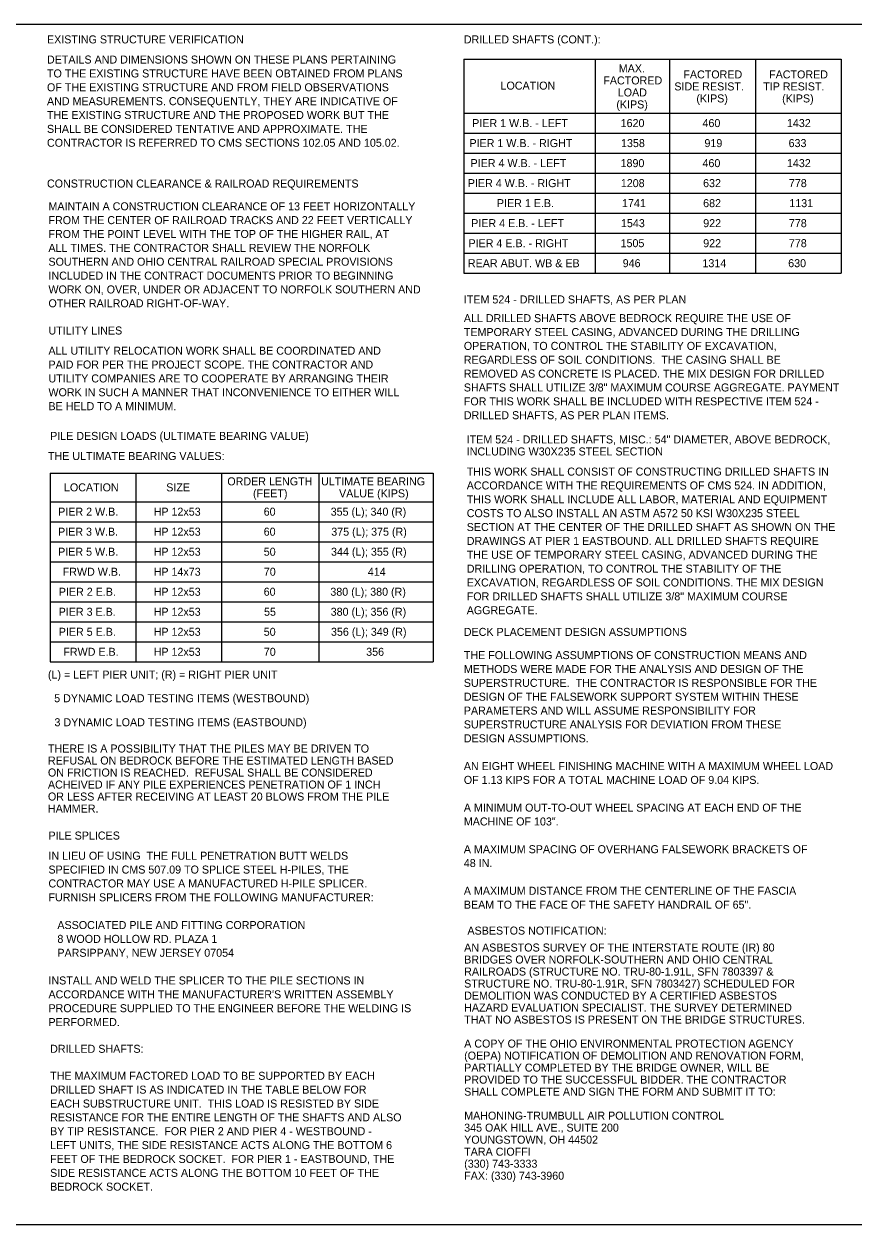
# Model space of a CAD drawing. Extents: x 1530552 to 1530730, y 675304 to 675366.
# Drawn here: x 1530707.49 to 1530722.01, y 675331.91 to 675352.91 of the extents above; entities that cross this region are included whole.
import ezdxf

# ---------------------------------------------------------------- set-up
doc = ezdxf.new("R2010")
doc.units = 0
doc.layers.add('BR_P_Gen_Text', color=7, linetype='Continuous')
doc.layers.add('Default', color=7, linetype='Continuous')

msp = doc.modelspace()

# ---------------------------------------------------------------- linework, layer by layer
at = {"layer": 'BR_P_Gen_Text'}
for p, q in [((1530715.188, 675352.298), (1530715.188, 675348.557)), ((1530715.188, 675352.298), (1530721.788, 675352.298)), ((1530717.488, 675352.298), (1530717.488, 675348.557)), ((1530718.788, 675352.298), (1530718.788, 675348.557)), ((1530720.288, 675352.298), (1530720.288, 675348.557)), ((1530721.788, 675352.298), (1530721.788, 675348.557)), ((1530715.188, 675351.357), (1530721.788, 675351.357)), ((1530715.188, 675351.007), (1530721.788, 675351.007)), ((1530715.188, 675350.657), (1530721.788, 675350.657)), ((1530715.188, 675350.307), (1530721.788, 675350.307)), ((1530715.188, 675349.957), (1530721.788, 675349.957)), ((1530715.188, 675349.607), (1530721.788, 675349.607)), ((1530715.188, 675349.257), (1530721.788, 675349.257)), ((1530715.188, 675348.907), (1530721.788, 675348.907)), ((1530715.188, 675348.557), (1530721.788, 675348.557)), ((1530707.951, 675345.062), (1530707.951, 675341.762)), ((1530707.951, 675345.062), (1530714.651, 675345.062)), ((1530709.451, 675345.062), (1530709.451, 675341.762)), ((1530710.951, 675345.062), (1530710.951, 675341.762)), ((1530712.651, 675345.062), (1530712.651, 675341.762)), ((1530714.651, 675345.062), (1530714.651, 675341.762)), ((1530707.951, 675344.562), (1530714.651, 675344.562)), ((1530707.951, 675344.212), (1530714.651, 675344.212)), ((1530707.951, 675343.862), (1530714.651, 675343.862)), ((1530707.951, 675343.512), (1530714.651, 675343.512)), ((1530707.951, 675343.162), (1530714.651, 675343.162)), ((1530707.951, 675342.812), (1530714.651, 675342.812)), ((1530707.951, 675342.462), (1530714.651, 675342.462)), ((1530707.951, 675342.112), (1530714.651, 675342.112)), ((1530707.951, 675341.762), (1530714.651, 675341.762))]:
    msp.add_line(p, q, dxfattribs=at)
msp.add_lwpolyline([(1530699.468, 675352.914), (1530729.968, 675352.914), (1530729.968, 675331.914), (1530699.468, 675331.914)], close=True, dxfattribs=at)

# ---------------------------------------------------------------- texts
for s, p in [('EXISTING STRUCTURE VERIFICATION', (1530707.896, 675352.575)), ('DRILLED SHAFTS (CONT.):', (1530715.188, 675352.575)), ('DETAILS AND DIMENSIONS SHOWN ON THESE PLANS PERTAINING ', (1530707.896, 675352.223)), ('TO THE EXISTING STRUCTURE HAVE BEEN OBTAINED FROM PLANS ', (1530707.896, 675351.98)), ('MAX. ', (1530717.898, 675352.068)), ('FACTORED', (1530719.028, 675351.963)), ('FACTORED', (1530720.528, 675351.963)), ('OF THE EXISTING STRUCTURE AND FROM FIELD OBSERVATIONS ', (1530707.896, 675351.738)), ('LOCATION', (1530715.83, 675351.767)), ('FACTORED', (1530717.628, 675351.858)), ('SIDE RESIST.', (1530718.87, 675351.753)), ('TIP RESIST.', (1530720.425, 675351.753)), ('AND MEASUREMENTS. CONSEQUENTLY, THEY ARE INDICATIVE OF ', (1530707.896, 675351.495)), ('LOAD', (1530717.881, 675351.648)), ('(KIPS)', (1530719.256, 675351.543)), ('(KIPS)', (1530720.756, 675351.543)), ('THE EXISTING STRUCTURE AND THE PROPOSED WORK BUT THE ', (1530707.896, 675351.253)), ('(KIPS)', (1530717.856, 675351.438)), ('PIER 1 W.B. - LEFT', (1530715.334, 675351.112)), ('1620', (1530717.931, 675351.112)), ('460', (1530719.363, 675351.112)), ('1432', (1530720.84, 675351.112)), ('SHALL BE CONSIDERED TENTATIVE AND APPROXIMATE. THE ', (1530707.896, 675351.011)), ('CONTRACTOR IS REFERRED TO CMS SECTIONS 102.05 AND 105.02.', (1530707.896, 675350.768)), ('PIER 1 W.B. - RIGHT', (1530715.286, 675350.762)), ('1358', (1530717.938, 675350.762)), ('919', (1530719.397, 675350.762)), ('633', (1530720.869, 675350.762)), ('PIER 4 W.B. - LEFT', (1530715.306, 675350.412)), ('1890', (1530717.93, 675350.412)), ('460', (1530719.363, 675350.412)), ('1432', (1530720.84, 675350.412)), ('CONSTRUCTION CLEARANCE & RAILROAD REQUIREMENTS', (1530707.896, 675350.055)), ('PIER 4 W.B. - RIGHT', (1530715.258, 675350.062)), ('1208', (1530717.934, 675350.062)), ('632', (1530719.373, 675350.062)), ('778', (1530720.874, 675350.062)), ('MAINTAIN A CONSTRUCTION CLEARANCE OF 13 FEET HORIZONTALLY ', (1530707.922, 675349.657)), ('PIER 1 E.B.', (1530715.767, 675349.712)), ('1741', (1530717.955, 675349.712)), ('682', (1530719.374, 675349.712)), ('1131', (1530720.881, 675349.712)), ('FROM THE CENTER OF RAILROAD TRACKS AND 22 FEET VERTICALLY ', (1530707.922, 675349.415)), ('PIER 4 E.B. - LEFT', (1530715.317, 675349.362)), ('1543', (1530717.937, 675349.362)), ('922', (1530719.375, 675349.362)), ('778', (1530720.874, 675349.362)), ('FROM THE POINT LEVEL WITH THE TOP OF THE HIGHER RAIL, AT ', (1530707.922, 675349.173)), ('PIER 4 E.B. - RIGHT', (1530715.269, 675349.012)), ('1505', (1530717.93, 675349.012)), ('922', (1530719.375, 675349.012)), ('778', (1530720.874, 675349.012)), ('ALL TIMES. THE CONTRACTOR SHALL REVIEW THE NORFOLK ', (1530707.922, 675348.93)), ('SOUTHERN AND OHIO CENTRAL RAILROAD SPECIAL PROVISIONS ', (1530707.922, 675348.688)), ('REAR ABUT. WB & EB', (1530715.259, 675348.662)), ('946', (1530717.967, 675348.662)), ('1314', (1530719.362, 675348.662)), ('630', (1530720.862, 675348.662)), ('INCLUDED IN THE CONTRACT DOCUMENTS PRIOR TO BEGINNING ', (1530707.922, 675348.445)), ('WORK ON, OVER, UNDER OR ADJACENT TO NORFOLK SOUTHERN AND ', (1530707.922, 675348.203)), ('OTHER RAILROAD RIGHT-OF-WAY.', (1530707.922, 675347.961)), ('ITEM 524 - DRILLED SHAFTS, AS PER PLAN', (1530715.188, 675348.028)), ('ALL DRILLED SHAFTS ABOVE BEDROCK REQUIRE THE USE OF ', (1530715.188, 675347.701)), ('UTILITY LINES', (1530707.922, 675347.485)), ('TEMPORARY STEEL CASING, ADVANCED DURING THE DRILLING ', (1530715.188, 675347.458)), ('ALL UTILITY RELOCATION WORK SHALL BE COORDINATED AND ', (1530707.922, 675347.132)), ('OPERATION, TO CONTROL THE STABILITY OF EXCAVATION, ', (1530715.188, 675347.216)), ('PAID FOR PER THE PROJECT SCOPE. THE CONTRACTOR AND ', (1530707.922, 675346.89)), ('REGARDLESS OF SOIL CONDITIONS.  THE CASING SHALL BE ', (1530715.188, 675346.973)), ('UTILITY COMPANIES ARE TO COOPERATE BY ARRANGING THEIR ', (1530707.922, 675346.647)), ('REMOVED AS CONCRETE IS PLACED. THE MIX DESIGN FOR DRILLED ', (1530715.188, 675346.731)), ('SHAFTS SHALL UTILIZE 3/8" MAXIMUM COURSE AGGREGATE. PAYMENT ', (1530715.188, 675346.489)), ('WORK IN SUCH A MANNER THAT INCONVENIENCE TO EITHER WILL ', (1530707.922, 675346.405)), ('FOR THIS WORK SHALL BE INCLUDED WITH RESPECTIVE ITEM 524 - ', (1530715.188, 675346.246)), ('BE HELD TO A MINIMUM.', (1530707.922, 675346.162)), ('DRILLED SHAFTS, AS PER PLAN ITEMS.', (1530715.188, 675346.004)), ('PILE DESIGN LOADS (ULTIMATE BEARING VALUE)', (1530707.951, 675345.642)), ('ITEM 524 - DRILLED SHAFTS, MISC.: 54" DIAMETER, ABOVE BEDROCK,', (1530715.239, 675345.58)), ('INCLUDING W30X235 STEEL SECTION', (1530715.239, 675345.37)), ('THE ULTIMATE BEARING VALUES:', (1530707.913, 675345.29)), ('THIS WORK SHALL CONSIST OF CONSTRUCTING DRILLED SHAFTS IN ', (1530715.239, 675345.018)), ('LOCATION', (1530708.193, 675344.742)), ('SIZE', (1530709.982, 675344.742)), ('ORDER LENGTH', (1530711.051, 675344.847)), ('ULTIMATE BEARING ', (1530712.69, 675344.847)), ('ACCORDANCE WITH THE REQUIREMENTS OF CMS 524. IN ADDITION, ', (1530715.239, 675344.776)), ('(FEET)', (1530711.5, 675344.637)), ('VALUE (KIPS)', (1530713.005, 675344.637)), ('THIS WORK SHALL INCLUDE ALL LABOR, MATERIAL AND EQUIPMENT ', (1530715.239, 675344.533)), ('355 (L); 340 (R)', (1530712.859, 675344.317)), ('PIER 2 W.B.', (1530708.092, 675344.317)), ('HP 12x53', (1530709.762, 675344.317)), ('60', (1530711.687, 675344.317)), ('COSTS TO ALSO INSTALL AN ASTM A572 50 KSI W30X235 STEEL ', (1530715.239, 675344.291)), ('PIER 3 W.B.', (1530708.09, 675343.967)), ('HP 12x53', (1530709.762, 675343.967)), ('60', (1530711.687, 675343.967)), ('375 (L); 375 (R)', (1530712.869, 675343.967)), ('SECTION AT THE CENTER OF THE DRILLED SHAFT AS SHOWN ON THE ', (1530715.239, 675344.049)), ('DRAWINGS AT PIER 1 EASTBOUND. ALL DRILLED SHAFTS REQUIRE ', (1530715.239, 675343.806)), ('PIER 5 W.B.', (1530708.091, 675343.617)), ('HP 12x53', (1530709.762, 675343.617)), ('50', (1530711.688, 675343.617)), ('344 (L); 355 (R)', (1530712.865, 675343.617)), ('THE USE OF TEMPORARY STEEL CASING, ADVANCED DURING THE ', (1530715.239, 675343.564)), ('DRILLING OPERATION, TO CONTROL THE STABILITY OF THE ', (1530715.239, 675343.321)), ('FRWD W.B.', (1530708.171, 675343.267)), ('HP 14x73', (1530709.762, 675343.267)), ('70', (1530711.689, 675343.267)), ('414', (1530713.509, 675343.267)), ('EXCAVATION, REGARDLESS OF SOIL CONDITIONS. THE MIX DESIGN ', (1530715.239, 675343.079)), ('PIER 2 E.B.', (1530708.103, 675342.917)), ('HP 12x53', (1530709.762, 675342.917)), ('60', (1530711.687, 675342.917)), ('380 (L); 380 (R)', (1530712.853, 675342.917)), ('FOR DRILLED SHAFTS SHALL UTILIZE 3/8" MAXIMUM COURSE ', (1530715.239, 675342.836)), ('PIER 3 E.B.', (1530708.101, 675342.567)), ('HP 12x53', (1530709.762, 675342.567)), ('55', (1530711.693, 675342.567)), ('380 (L); 356 (R)', (1530712.859, 675342.567)), ('AGGREGATE.', (1530715.239, 675342.594)), ('356 (L); 349 (R)', (1530712.864, 675342.217)), ('PIER 5 E.B.', (1530708.102, 675342.217)), ('HP 12x53', (1530709.762, 675342.217)), ('50', (1530711.688, 675342.217)), ('DECK PLACEMENT DESIGN ASSUMPTIONS', (1530715.188, 675342.215)), ('FRWD E.B.', (1530708.182, 675341.867)), ('HP 12x53', (1530709.762, 675341.867)), ('70', (1530711.689, 675341.867)), ('356', (1530713.48, 675341.867)), ('THE FOLLOWING ASSUMPTIONS OF CONSTRUCTION MEANS AND', (1530715.188, 675341.809)), ('(L) = LEFT PIER UNIT; (R) = RIGHT PIER UNIT', (1530707.913, 675341.469)), ('METHODS WERE MADE FOR THE ANALYSIS AND DESIGN OF THE', (1530715.188, 675341.566)), ('SUPERSTRUCTURE.  THE CONTRACTOR IS RESPONSIBLE FOR THE', (1530715.188, 675341.324)), ('5 DYNAMIC LOAD TESTING ITEMS (WESTBOUND)', (1530708.022, 675341.055)), ('DESIGN OF THE FALSEWORK SUPPORT SYSTEM WITHIN THESE', (1530715.188, 675341.082)), ('PARAMETERS AND WILL ASSUME RESPONSIBILITY FOR', (1530715.188, 675340.839)), ('3 DYNAMIC LOAD TESTING ITEMS (EASTBOUND)', (1530708.027, 675340.635)), ('SUPERSTRUCTURE ANALYSIS FOR DEVIATION FROM THESE', (1530715.188, 675340.597)), ('DESIGN ASSUMPTIONS.', (1530715.188, 675340.354)), ('THERE IS A POSSIBILITY THAT THE PILES MAY BE DRIVEN TO', (1530707.913, 675340.176)), ('REFUSAL ON BEDROCK BEFORE THE ESTIMATED LENGTH BASED', (1530707.913, 675339.966)), ('ON FRICTION IS REACHED.  REFUSAL SHALL BE CONSIDERED', (1530707.913, 675339.756)), ('AN EIGHT WHEEL FINISHING MACHINE WITH A MAXIMUM WHEEL LOAD', (1530715.188, 675339.869)), ('ACHEIVED IF ANY PILE EXPERIENCES PENETRATION OF 1 INCH', (1530707.913, 675339.546)), ('OF 1.13 KIPS FOR A TOTAL MACHINE LOAD OF 9.04 KIPS.', (1530715.188, 675339.627)), ('OR LESS AFTER RECEIVING AT LEAST 20 BLOWS FROM THE PILE', (1530707.913, 675339.336)), ('HAMMER.', (1530707.913, 675339.126)), ('A MINIMUM OUT-TO-OUT WHEEL SPACING AT EACH END OF THE', (1530715.188, 675339.142)), ('MACHINE OF 103".', (1530715.188, 675338.9)), ('PILE SPLICES', (1530707.922, 675338.654)), ('IN LIEU OF USING  THE FULL PENETRATION BUTT WELDS ', (1530707.922, 675338.301)), ('A MAXIMUM SPACING OF OVERHANG FALSEWORK BRACKETS OF', (1530715.188, 675338.415)), ('SPECIFIED IN CMS 507.09 TO SPLICE STEEL H-PILES, THE ', (1530707.922, 675338.059)), ('48 IN.', (1530715.188, 675338.173)), ('CONTRACTOR MAY USE A MANUFACTURED H-PILE SPLICER. ', (1530707.922, 675337.816)), ('A MAXIMUM DISTANCE FROM THE CENTERLINE OF THE FASCIA', (1530715.188, 675337.688)), ('FURNISH SPLICERS FROM THE FOLLOWING MANUFACTURER:', (1530707.922, 675337.574)), ('BEAM TO THE FACE OF THE SAFETY HANDRAIL OF 65".', (1530715.188, 675337.445)), ('   ASSOCIATED PILE AND FITTING CORPORATION', (1530707.922, 675337.089)), ('   8 WOOD HOLLOW RD. PLAZA 1', (1530707.922, 675336.847)), ('   PARSIPPANY, NEW JERSEY 07054', (1530707.922, 675336.604)), ('INSTALL AND WELD THE SPLICER TO THE PILE SECTIONS IN ', (1530707.922, 675336.12)), ("ACCORDANCE WITH THE MANUFACTURER'S WRITTEN ASSEMBLY ", (1530707.922, 675335.877)), ('PROCEDURE SUPPLIED TO THE ENGINEER BEFORE THE WELDING IS ', (1530707.922, 675335.635)), ('PERFORMED.', (1530707.922, 675335.392)), ('DRILLED SHAFTS:', (1530707.951, 675334.925)), ('THE MAXIMUM FACTORED LOAD TO BE SUPPORTED BY EACH ', (1530707.951, 675334.453)), ('DRILLED SHAFT IS AS INDICATED IN THE TABLE BELOW FOR ', (1530707.951, 675334.211)), ('EACH SUBSTRUCTURE UNIT.  THIS LOAD IS RESISTED BY SIDE ', (1530707.951, 675333.968)), ('RESISTANCE FOR THE ENTIRE LENGTH OF THE SHAFTS AND ALSO ', (1530707.951, 675333.726)), ('BY TIP RESISTANCE.  FOR PIER 2 AND PIER 4 - WESTBOUND - ', (1530707.951, 675333.484)), ('LEFT UNITS, THE SIDE RESISTANCE ACTS ALONG THE BOTTOM 6 ', (1530707.951, 675333.241)), ('FEET OF THE BEDROCK SOCKET.  FOR PIER 1 - EASTBOUND, THE ', (1530707.951, 675332.999)), ('SIDE RESISTANCE ACTS ALONG THE BOTTOM 10 FEET OF THE ', (1530707.951, 675332.756)), ('BEDROCK SOCKET.', (1530707.951, 675332.514))]:
    msp.add_text(s, height=0.14, dxfattribs=at).set_placement(p)
at = {"layer": 'Default'}
for s, p in [('ASBESTOS NOTIFICATION:', (1530715.251, 675336.992)), ('AN ASBESTOS SURVEY OF THE INTERSTATE ROUTE (IR) 80 ', (1530715.194, 675336.696)), ('BRIDGES OVER NORFOLK-SOUTHERN AND OHIO CENTRAL ', (1530715.194, 675336.486)), ('RAILROADS (STRUCTURE NO. TRU-80-1.91L, SFN 7803397 & ', (1530715.194, 675336.276)), ('STRUCTURE NO. TRU-80-1.91R, SFN 7803427) SCHEDULED FOR ', (1530715.194, 675336.066)), ('DEMOLITION WAS CONDUCTED BY A CERTIFIED ASBESTOS ', (1530715.194, 675335.856)), ('HAZARD EVALUATION SPECIALIST. THE SURVEY DETERMINED ', (1530715.194, 675335.646)), ('THAT NO ASBESTOS IS PRESENT ON THE BRIDGE STRUCTURES.', (1530715.194, 675335.436)), ('A COPY OF THE OHIO ENVIRONMENTAL PROTECTION AGENCY ', (1530715.194, 675335.016)), ('(OEPA) NOTIFICATION OF DEMOLITION AND RENOVATION FORM, ', (1530715.194, 675334.806)), ('PARTIALLY COMPLETED BY THE BRIDGE OWNER, WILL BE ', (1530715.194, 675334.596)), ('PROVIDED TO THE SUCCESSFUL BIDDER. THE CONTRACTOR ', (1530715.194, 675334.386)), ('SHALL COMPLETE AND SIGN THE FORM AND SUBMIT IT TO:', (1530715.194, 675334.176)), ('MAHONING-TRUMBULL AIR POLLUTION CONTROL', (1530715.194, 675333.756)), ('345 OAK HILL AVE., SUITE 200', (1530715.194, 675333.546)), ('YOUNGSTOWN, OH 44502', (1530715.194, 675333.336)), ('TARA CIOFFI', (1530715.194, 675333.126)), ('(330) 743-3333', (1530715.194, 675332.916)), ('FAX: (330) 743-3960', (1530715.194, 675332.706))]:
    msp.add_text(s, height=0.14, dxfattribs=at).set_placement(p)

doc.saveas('drawing.dxf')
